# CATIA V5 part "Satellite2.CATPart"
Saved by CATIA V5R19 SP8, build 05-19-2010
Part number: Satellite2
Bounding box of the stored display mesh (mm): x 0 to 14, y -50.311 to -10.311, z -37.5 to 2.5
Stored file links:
  G:\EU_thinkMotion\CFAO_2010\SIL_groupe2\SIL_groupe2\msauret\Brevet_Sauret_parametre\Satellite2.CATPart
  F:\Brevet_Sauret paramétré\Product3.CATProduct
  G:\EU_thinkMotion\CFAO_2010\SIL_groupe2\SIL_groupe2\msauret\Brevet_Sauret_parametre\Satellite1.CATPart
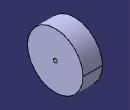
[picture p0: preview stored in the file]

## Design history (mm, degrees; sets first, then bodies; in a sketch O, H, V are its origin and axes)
Set1
  Plane1: linked copy from another document
  Point1: linked copy from another document
  Plane2: linked copy from another document
  Plane3: linked copy from another document
  Point2: linked copy from another document
  DatumCurve1: linked copy from another document
Body1 (main body)
  Sketch1 on Plane1, origin (0, 0, 0), H (0, 1, 0), V (0, 0, 1)
    circle A1 centre (-30.311, -17.5) radius 20
    point P1 (-30.311, -17.5)
    reference projected point E1 (-30.311, -17.5) from Point1
    distance P1 E1 = 0
  Pad1: profile Sketch1, direction (1, 0, 0), up to Plane2
  Sketch2 on Plane1, origin (0, 0, 0), H (0, 1, 0), V (0, 0, 1)
    circle A1 centre (-30.311, -17.5) radius 1.5
    point P1 (-30.311, -17.5)
    reference projected point E1 (-30.311, -17.5) from Point1
    distance P1 E1 = 0
  Pocket1: profile Sketch2, direction (-1, 0, 0), up to Plane2
  Sketch3 on start face of Pad1, origin (0, 0, 0), H (0, -1, 0), V (0, 0, 1)
    circle A1 centre (30.311, -17.5) radius 20
    point P1 (30.311, -17.5)
    reference projected point E1 (30.311, -17.5) from Point1
    distance P1 E1 = 0
  Plane4: type Offset, RefPlane Plane3, Offset 9
  Sketch4 on Plane4, origin (9, 0, 0), H (0, 1, 0), V (0, 0, 1)
    circle A1 centre (-30.311, -17.5) radius 20
    reference projected circle E1 centre (-30.311, -17.5) radius 20 from edge [face of Pad1 from Sketch1.A1 | end face of Pad1]
    coincidence: A1 E1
